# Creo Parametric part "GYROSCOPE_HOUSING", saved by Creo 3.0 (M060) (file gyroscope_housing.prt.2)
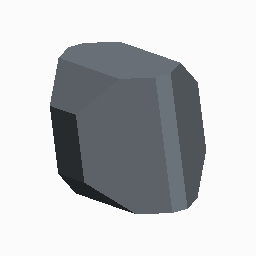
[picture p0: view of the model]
Units: millimeter Kilogram Sec (mmKs); MM, KILOGRAM, SECS
Materials in the file: ALUMINUM_ALLOY_6061_T6

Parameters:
  PTC_MATERIAL_NAME = "ALUMINUM_ALLOY_6061_T6"

Other parameters: D16

Created from: INLBS_PART_SOLID.PRT

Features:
  1. datum plane "RIGHT"
  2. datum plane "TOP"
  3. datum plane "FRONT"
  4. coordinate system
  5. sketch "Sketch 1"
  6. extrusion "Extrude 1"
  7. chamfer "Chamfer 1"
  8. chamfer "Chamfer 2"
  9. chamfer "Chamfer 3"
  10. chamfer "Chamfer 4"
  11. shell "Shell 1"
  12. datum point "GYROSCOPE_ENTER_PT", "GYROSCOPE_CENTER_PT"

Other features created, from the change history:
  chamfer "Chamfer 1"
  datum point "PNT0"

Surfaces: 31 plane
